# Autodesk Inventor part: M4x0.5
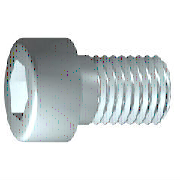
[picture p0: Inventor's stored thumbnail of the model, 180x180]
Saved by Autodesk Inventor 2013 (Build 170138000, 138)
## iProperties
IsCustomPart: 1
Company: 한국ATC센터
Created: 2014-11
Part Number: M4x0.5
Material: 강, 연강
Description: 6각머리 태핑 나사
Document SubType Name: Modeling
Standard: KS B 1003
Designer: KYOUNG IL JANG
Standards Organization: KS
Language: ko-KR
Size Designation: M 4 x 16
Categories: <MemberInstance><Categories><Category DisplayName="조임쇠" InternalName="e4da775c-781d-43d5-af7c-5136215cf5a6" Mnemonic="FSTN"><Category DisplayName="볼트" InternalN
Density: 7.86 g/cm^3
Mass: 2.62973 g
Surface Area: 3.81119 cm^2
Volume: 0.334572 cm^3
Author: KYOUNG IL JANG
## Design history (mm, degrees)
sketch "스케치1"
  geometry: L1 (-1, 0)-(16, 0); L2 (16, 0)-(16, 2); L3 (16, 2)-(1.75, 2); L4 (1.75, 2)-(1.32, 2); L5 (1.32, 2)-(0, 2); L6 (0, 2)-(0, 3.5); L7 (0, 3.5)-(-4, 3.5); L8 (-4, 3.5)-(-4, 1.732); L9 (-4, 1.732)-(-2, 1.732); L10 (-2, 1.732)-(-1, 0); L11 (-8, 0)-(20, 0) reference; L12 (0, -0.7)-(0, 4.2) reference; L13 (1.75, 2)-(0, 2)
  constraints: 22 end point, 6 parallel, 2 collinear, 2 perpendicular, 1 horizontal, 1 point on line
  dimensions: "d1" = 14.25 distance from line of L3.end L2 (= GEL); "d2" = 0.42952 distance of L4.end L3.end (computed from GAL); "d3" = 4 distance between parallel lines of L8 L6 (= KOH); "d4" = 2 distance of L8.end L9.end (= INTI); "d5" = 60 deg angle of L10 L1; "d6" = 4 diameter of L3 L1 (= GD); "d7" = 4 diameter of L5 L1 (= BDM); "d8" = 3.4641 diameter of L9 L1 (= 1.1547 x SW); "d9" = 7 diameter of L7 L1 (= KOD); "d26" = 16 distance between parallel lines of L12 L2 (= NLG)
revolve "본체" sketch "스케치1" stored, may be unused: angle "d10" = 90 deg
sketch "스케치2"
  geometry: L1 (0, -4.9)-(0, 4.9) reference; L2 (-4.9, 0)-(4.9, 0) reference; L3 (1.732, 0)-(0.866, -1.5); L4 (0.866, -1.5)-(-0.866, -1.5); L5 (-0.866, -1.5)-(-1.732, 0); L6 (-1.732, 0)-(-0.866, 1.5); L7 (-0.866, 1.5)-(0.866, 1.5); L8 (0.866, 1.5)-(1.732, 0); 2 further points
  constraints: 12 end point, 1 coincident, 1 horizontal alignment, 1 point on line, 12 other
extrude "슬롯" join sketch "스케치2" stored distance "d11" = 10; taper "d12" = 0 deg
workplane "Work Plane1"
fillet "Fillet2" dims "d30" = 0.1 (= R)
body "Solid1"
fillet "모깎기1" dims "d17" = 0.4 (= RR)
feature "스레드" dims "d13" = 14.25 (= GEL), "d14" = 0
chamfer "모따기1" distance "d15" = 0.42941 (= -0.5 x SPD + 0.5 x GD); stored, may be unused: second distance "d16" = 0.42941 (= GUL), angle "d27" = 45 deg
other parameters: "GD" = 4 (= NND) [user parameter; used in 2 equation terms], "NLG" = 16 [user parameter; used in 1 equation term], "GEL" = 14.25 [user parameter; used in 2 equation terms], "KOD" = 7 [user parameter; used in 1 equation term], "KOH" = 4 [user parameter; used in 1 equation term], "INTI" = 2 [user parameter; used in 1 equation term], "GAL" = 0.42941 (= 0.61345 x PTC) [user parameter; used in 1 equation term], "GUL" = 0.42941 (= 0.61345 x PTC) [user parameter; used in 1 equation term], "BDM" = 4 (= NND) [user parameter; used in 1 equation term], "SW" = 3 [user parameter; used in 2 equation terms], "RR" = 0.4 [user parameter; used in 1 equation term], "SPD" = 3.14117 (= NND - 1.2269 x PTC) [user parameter; used in 1 equation term], "d19" = 0, "d28" = 0, "d29" = 0, "R" = 0.1 [user parameter; used in 1 equation term], "PHH" = 0.2 [user parameter], "GD1" = 3.14117 (= THREADDIA - 1.2269 x PTC) [user parameter], "THREADDIA" = 4 [user parameter; used in 1 equation term], "FAWI" = 45 deg [user parameter], "TPU" = 14.28571 (computed from PTC) [user parameter], "PTC" = 0.7 [user parameter; used in 5 equation terms], "NND" = 4 [user parameter; used in 3 equation terms], "TOA" = 30 deg [user parameter], "E0" = 3.465 (= 1.155 x SW) [user parameter]
